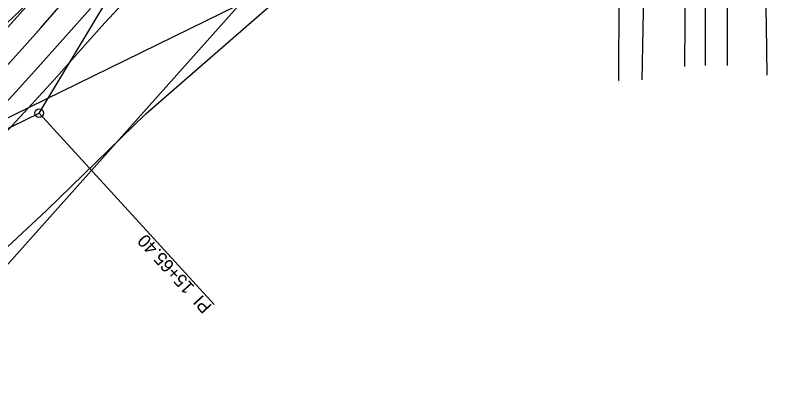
# Model space of a CAD drawing. Extents: x 1674300 to 1677920, y 225056 to 231852.
# Drawn here: x 1677063.6 to 1677413, y 227799.6 to 227976.6 of the extents above; entities that cross this region are included whole.
import ezdxf

# ---------------------------------------------------------------- set-up
doc = ezdxf.new("R2010")
doc.units = 0
for name, color, linetype in [('R_Horz Alg', 7, 'Continuous'), ('R_Horz Alg Annot', 7, 'Continuous'), ('R_Proposed Const Limits_Fill', 7, 'Continuous'), ('R_Proposed Road_Lane', 7, 'Continuous'), ('R_Proposed Road_Shoulder', 7, 'Continuous'), ('S_DITCHLINE', 7, 'Continuous'), ('S_EDGE_PAVEMENT', 7, 'Continuous'), ('S_ELECTRIC_UTILITIES', 7, 'Continuous'), ('S_EXIST_ROW', 7, 'Continuous'), ('S_FIBER_OPTIC_CABLE', 7, 'Continuous'), ('S_PAVEMENT_CROWN', 7, 'Continuous'), ('S_SHOULDER', 7, 'Continuous'), ('S_UTL_PT_SYM', 7, 'Continuous')]:
    doc.layers.add(name, color=color, linetype=linetype)

msp = doc.modelspace()

# ---------------------------------------------------------------- linework, layer by layer
at = {"layer": 'R_Horz Alg'}
for centre, radius, end in [((1675928.16, 228988.54), 1449, 0.80558), ((1676402.48, 228665.51), 954.93, 328.88259)]:
    msp.add_arc(centre, radius, 296.0624, end, dxfattribs=at)
at = {"layer": 'R_Horz Alg Annot'}
for p, q in [((1677074.66, 227931.25), (1677220, 228172.01)), ((1676564.78, 227686.88), (1677389.93, 228090.45)), ((1676822.03, 227807.69), (1677074.66, 227931.25))]:
    msp.add_line(p, q, dxfattribs=at)
msp.add_lwpolyline([(1677074.66, 227931.25), (1677155.69, 227842.73)], dxfattribs=at)
msp.add_circle((1677074.66, 227931.25), 2, dxfattribs=at)
at = {"layer": 'R_Proposed Const Limits_Fill'}
msp.add_arc((1676364.65, 228668.23), 963.36, 309.06481, 319.55161, dxfattribs=at)
at = {"layer": 'R_Proposed Road_Lane'}
msp.add_lwpolyline([(1676953.5, 227863.64), (1676956.64, 227866.52), (1676972.6, 227881.4), (1676988.37, 227896.5), (1676996.17, 227904.12), (1677007.75, 227915.68), (1677022.13, 227930.45), (1677031.62, 227940.39), (1677041.04, 227950.41), (1677050.47, 227960.42), (1677064.47, 227975.57), (1677071.28, 227983.29), (1677077.87, 227991.2), (1677081.05, 227995.24), (1677086, 228001.89), (1677089.18, 228006.41), (1677095.28, 228015.66), (1677102.54, 228027.13)], dxfattribs=at)
msp.add_arc((1676402.48, 228665.51), 947.43, 296.0624, 317.63818, dxfattribs=at)
at = {"layer": 'R_Proposed Road_Shoulder'}
msp.add_arc((1676402.48, 228665.51), 941.43, 296.0624, 317.05629, dxfattribs=at)
at = {"layer": 'S_DITCHLINE'}
for points in [[(1677411.34, 227948.81), (1677410.93, 227971.75), (1677410.52, 227994.7), (1677410.65, 228010.19), (1677410.77, 228025.67), (1677410.6, 228040.23), (1677410.43, 228054.8), (1677410.25, 228069.36), (1677410.08, 228083.92), (1677410.62, 228100.96), (1677411.16, 228118), (1677411.12, 228132.07), (1677411.08, 228146.13), (1677411.04, 228160.19), (1677411, 228174.26), (1677412.02, 228192.39), (1677413.03, 228210.53), (1677412.69, 228226.29), (1677412.54, 228228.6)], [(1677353.55, 227946.6), (1677353.97, 227970.29), (1677354.38, 227993.98), (1677353.74, 228008.93), (1677353.09, 228023.88), (1677354.22, 228046.14), (1677355.36, 228068.4), (1677354.45, 228091.59), (1677353.55, 228114.78), (1677355.39, 228135.08), (1677355.46, 228148.71)]]:
    msp.add_lwpolyline(points, dxfattribs=at)
at = {"layer": 'S_EDGE_PAVEMENT'}
for points in [[(1677050.47, 227960.42), (1677064.47, 227975.57), (1677071.28, 227983.29), (1677077.87, 227991.2), (1677081.05, 227995.24), (1677086, 228001.89), (1677089.18, 228006.41), (1677095.28, 228015.66), (1677103.13, 228028.07), (1677110.98, 228040.48), (1677123.03, 228059.15), (1677135.07, 228077.82), (1677142.69, 228089.53), (1677150.3, 228101.23), (1677162.42, 228119.68), (1677174.53, 228138.13), (1677187.58, 228158.03), (1677200.63, 228177.93), (1677210.53, 228193.87), (1677220.43, 228209.81), (1677230.72, 228227.78), (1677241.01, 228245.75)], [(1677373.34, 227987.15), (1677373.29, 227973.45), (1677373.05, 227952.85)], [(1677393.01, 227953.24), (1677392.99, 227973.14), (1677393.01, 227986.86)], [(1677050.82, 227926.92), (1677064.06, 227941.19), (1677075.56, 227953.94), (1677090.78, 227971.04), (1677098.41, 227979.59)]]:
    msp.add_lwpolyline(points, dxfattribs=at)
at = {"layer": 'S_ELECTRIC_UTILITIES'}
msp.add_line((1677342.78, 227946.34), (1677343.16, 228080.48), dxfattribs=at)
at = {"layer": 'S_EXIST_ROW'}
msp.add_line((1677045.25, 227844.61), (1677191.98, 228009.21), dxfattribs=at)
msp.add_arc((1675926.71, 228989.39), 1410.53, 295.94359, 0.85682, dxfattribs=at)
at = {"layer": 'S_FIBER_OPTIC_CABLE'}
for p, q in [((1677124.03, 227930.86), (1677206.22, 228002.56)), ((1677078.18, 227886.24), (1677124.03, 227930.86)), ((1676993.59, 227807.69), (1677078.18, 227886.24))]:
    msp.add_line(p, q, dxfattribs=at)
at = {"layer": 'S_PAVEMENT_CROWN'}
for points in [[(1677056.99, 227949.95), (1677068.17, 227962.37), (1677075.53, 227970.74), (1677090.09, 227987.61)], [(1677382.81, 227953.22), (1677382.74, 227973.42), (1677382.8, 227987.07)]]:
    msp.add_lwpolyline(points, dxfattribs=at)
at = {"layer": 'S_SHOULDER'}
msp.add_lwpolyline([(1677056.53, 227919.47), (1677069.55, 227933.42), (1677081.45, 227946.55), (1677097.2, 227964.17), (1677105.11, 227972.94), (1677117.45, 227986.37)], dxfattribs=at)
at = {"layer": 'S_UTL_PT_SYM'}
for points in [[(1677342.78, 227946.34), (1677342.78, 227946.39), (1677342.78, 227946.34), (1677342.73, 227946.34), (1677342.78, 227946.34), (1677342.78, 227946.29), (1677342.78, 227946.34), (1677342.83, 227946.34)], [(1677124.03, 227930.86), (1677124.03, 227930.91), (1677124.03, 227930.86), (1677123.98, 227930.86), (1677124.03, 227930.86), (1677124.03, 227930.81), (1677124.03, 227930.86), (1677124.08, 227930.86)], [(1677078.18, 227886.24), (1677078.18, 227886.29), (1677078.18, 227886.24), (1677078.13, 227886.24), (1677078.18, 227886.24), (1677078.18, 227886.19), (1677078.18, 227886.24), (1677078.23, 227886.24)]]:
    msp.add_lwpolyline(points, dxfattribs=at)

# ---------------------------------------------------------------- texts
at = {"layer": 'R_Horz Alg Annot'}
msp.add_text('PI  15+65.40', height=6, rotation=132.4725, dxfattribs=at).set_placement((1677154.95, 227842.06))

doc.saveas('drawing.dxf')
